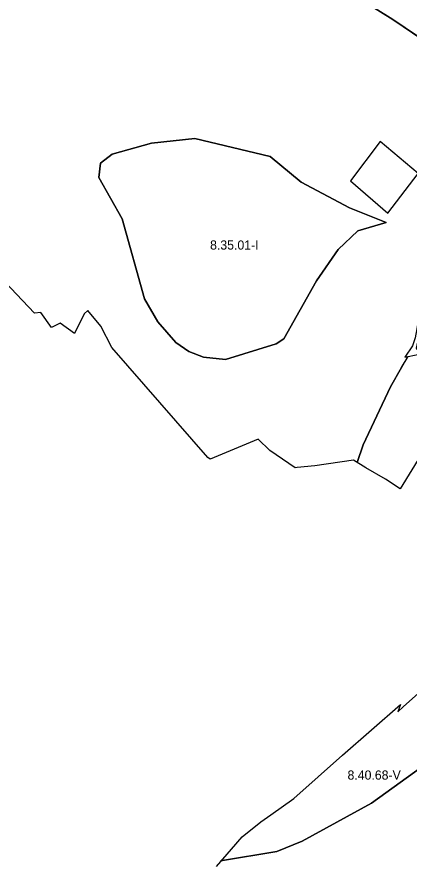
# Model space of a CAD drawing. Extents: x -547623 to -533936, y -1096714 to -1086523.
# Drawn here: x -542784 to -542357, y -1092131 to -1091207 of the extents above; entities that cross this region are included whole.
import ezdxf

# ---------------------------------------------------------------- set-up
doc = ezdxf.new("R2010")
doc.units = 0
doc.layers.add('Vrstva 27', color=7, linetype='Continuous')
doc.layers.add('Vrstva 28', color=7, linetype='Continuous')

msp = doc.modelspace()

# ---------------------------------------------------------------- linework, layer by layer
at = {"layer": 'Vrstva 28'}
for p, q in [((-542470.5, -1091150), (-542375, -1091210)), ((-542375, -1091210), (-542470.5, -1091150)), ((-542375, -1091210), (-542332, -1091239)), ((-542332, -1091239), (-542375, -1091210)), ((-542680.5, -1091356.5), (-542637.5, -1091344.5)), ((-542637.5, -1091344.5), (-542680.5, -1091356.5)), ((-542637.5, -1091344.5), (-542590.5, -1091339.5)), ((-542590.5, -1091339.5), (-542637.5, -1091344.5)), ((-542590.5, -1091339.5), (-542508.5, -1091359)), ((-542508.5, -1091359), (-542590.5, -1091339.5)), ((-542693, -1091366.5), (-542680.5, -1091356.5)), ((-542680.5, -1091356.5), (-542693, -1091366.5)), ((-542508.5, -1091359), (-542474.5, -1091387)), ((-542474.5, -1091387), (-542508.5, -1091359)), ((-542695, -1091382), (-542693, -1091366.5)), ((-542693, -1091366.5), (-542695, -1091382)), ((-542669.5, -1091427), (-542695, -1091382)), ((-542695, -1091382), (-542669.5, -1091427)), ((-542474.5, -1091387), (-542422, -1091415)), ((-542422, -1091415), (-542474.5, -1091387)), ((-542422, -1091415), (-542382, -1091431)), ((-542382, -1091431), (-542422, -1091415)), ((-542645, -1091514), (-542669.5, -1091427)), ((-542669.5, -1091427), (-542645, -1091514)), ((-542382, -1091431), (-542413, -1091440)), ((-542413, -1091440), (-542382, -1091431)), ((-542413, -1091440), (-542434.5, -1091460.5)), ((-542434.5, -1091460.5), (-542413, -1091440)), ((-542434.5, -1091460.5), (-542458, -1091494.5)), ((-542458, -1091494.5), (-542434.5, -1091460.5)), ((-542458, -1091494.5), (-542493.5, -1091557.5)), ((-542493.5, -1091557.5), (-542458, -1091494.5)), ((-542630.5, -1091539), (-542645, -1091514)), ((-542645, -1091514), (-542630.5, -1091539)), ((-542611, -1091561.5), (-542630.5, -1091539)), ((-542630.5, -1091539), (-542611, -1091561.5)), ((-542493.5, -1091557.5), (-542502, -1091563)), ((-542502, -1091563), (-542493.5, -1091557.5)), ((-542597, -1091571.5), (-542611, -1091561.5)), ((-542611, -1091561.5), (-542597, -1091571.5)), ((-542502, -1091563), (-542557, -1091580)), ((-542557, -1091580), (-542502, -1091563)), ((-542581, -1091577.5), (-542597, -1091571.5)), ((-542597, -1091571.5), (-542581, -1091577.5)), ((-542557, -1091580), (-542581, -1091577.5)), ((-542581, -1091577.5), (-542557, -1091580)), ((-542358.36, -1091577.01), (-542365.23, -1091588.85)), ((-542365.23, -1091588.85), (-542377.5, -1091610)), ((-542377.5, -1091610), (-542407, -1091673)), ((-542407, -1091673), (-542413.73, -1091692.28)), ((-542398, -1092063), (-542310.5, -1091999.5)), ((-542310.5, -1091999.5), (-542398, -1092063)), ((-542473.5, -1092104.5), (-542398, -1092063)), ((-542398, -1092063), (-542473.5, -1092104.5)), ((-542501, -1092115.5), (-542473.5, -1092104.5)), ((-542473.5, -1092104.5), (-542501, -1092115.5)), ((-542562.38, -1092125.97), (-542501, -1092115.5)), ((-542501, -1092115.5), (-542562.38, -1092125.97))]:
    msp.add_line(p, q, dxfattribs=at)
for points in [[(-542470.5, -1091150), (-542375, -1091210), (-542332, -1091239), (-542288.5, -1091278), (-542254, -1091314), (-542238, -1091340.5), (-542233.12, -1091370.25)], [(-542493.5, -1091557.5), (-542458, -1091494.5), (-542434.5, -1091460.5), (-542413, -1091440), (-542382, -1091431), (-542422, -1091415), (-542474.5, -1091387), (-542508.5, -1091359), (-542590.5, -1091339.5), (-542637.5, -1091344.5), (-542680.5, -1091356.5), (-542693, -1091366.5), (-542695, -1091382), (-542669.5, -1091427), (-542645, -1091514), (-542630.5, -1091539), (-542611, -1091561.5), (-542597, -1091571.5), (-542581, -1091577.5), (-542557, -1091580), (-542502, -1091563), (-542493.5, -1091557.5)], [(-542421.04, -1091385.69), (-542380.14, -1091420.72), (-542347.44, -1091377.7), (-542388.57, -1091342.81), (-542421.04, -1091385.69)], [(-542309.83, -1091479.9), (-542332.08, -1091461.23), (-542334.15, -1091462.33), (-542335.5, -1091463.49), (-542336.64, -1091464.7), (-542337.45, -1091467), (-542342.34, -1091507.21), (-542348.63, -1091546.81), (-542350.46, -1091556.49), (-542353.46, -1091565.22), (-542361.8, -1091577.48), (-542347.64, -1091574.68), (-542346.13, -1091571.83), (-542349.02, -1091567.94), (-542346.76, -1091557.93), (-542333.1, -1091532.96), (-542336.05, -1091529.74), (-542336.97, -1091519.95), (-542335.99, -1091512.51), (-542331.93, -1091504.44), (-542319.71, -1091491.97), (-542309.83, -1091479.9)], [(-542344.3, -1091684.07), (-542366.69, -1091720.95), (-542382.78, -1091710.52), (-542404.34, -1091698.18), (-542417.57, -1091689.6), (-542459.69, -1091695.93), (-542479.12, -1091697.75), (-542481.34, -1091697.96), (-542508.64, -1091679.19), (-542521.43, -1091666.8), (-542573.55, -1091688.64), (-542576.08, -1091686.72), (-542680.9, -1091567.22), (-542692.87, -1091543.99), (-542706.94, -1091526.88), (-542711, -1091530.5), (-542721.49, -1091551.88), (-542737.1, -1091540.66), (-542746.37, -1091545.11), (-542757.98, -1091529), (-542764.89, -1091529.82), (-542804, -1091488.75)], [(-542413.73, -1091692.28), (-542407, -1091673), (-542377.5, -1091610), (-542365.23, -1091588.85), (-542358.22, -1091576.77)], [(-542566.98, -1092132.15), (-542538.71, -1092099.56), (-542518.46, -1092083.18), (-542507.7, -1092075.65), (-542482.46, -1092057.98), (-542429.48, -1092010.84), (-542366.63, -1091955.73), (-542369.29, -1091963.47), (-542363.06, -1091957.81), (-542324.59, -1091923.69)]]:
    msp.add_lwpolyline(points, dxfattribs=at)

# ---------------------------------------------------------------- texts
at = {"layer": 'Vrstva 27'}
for s, p in [('8.35.01-I', (-542573.8, -1091460.48)), ('8.40.68-V', (-542424.18, -1092037.43))]:
    msp.add_text(s, height=10, dxfattribs=at).set_placement(p)

doc.saveas('drawing.dxf')
